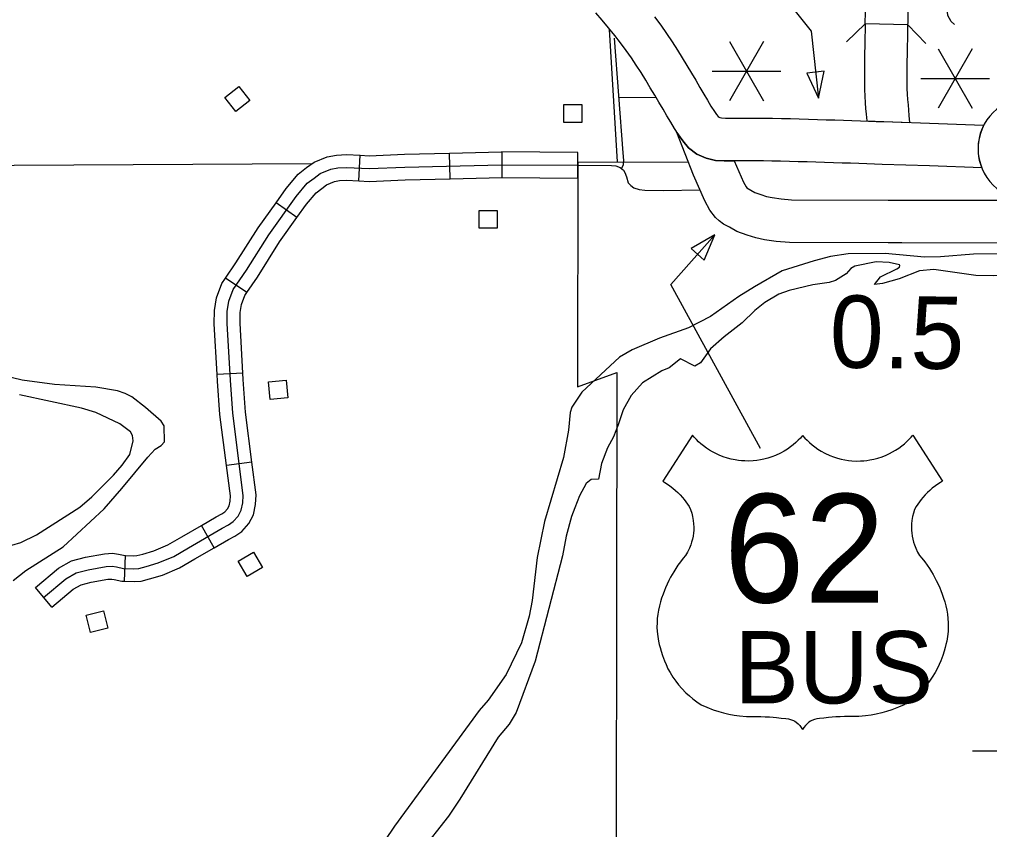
# Model space of a CAD drawing. Extents: x 1370130 to 1380143, y 377636 to 380256.
# Drawn here: x 1377311.5 to 1377470.1, y 378901.1 to 379033.5 of the extents above; entities that cross this region are included whole.
import ezdxf

# ---------------------------------------------------------------- set-up
doc = ezdxf.new("R2010")
doc.units = 0
for name, color, linetype in [('Level 10', 7, 'Continuous'), ('Level 15', 7, 'Continuous'), ('Level 22', 7, 'Continuous'), ('Level 24', 7, 'Continuous'), ('Level 31', 7, 'Continuous'), ('Level 32', 7, 'Continuous'), ('Level 33', 7, 'Continuous'), ('Level 34', 7, 'Continuous'), ('Level 35', 7, 'Continuous'), ('Level 37', 7, 'Continuous'), ('Level 48', 7, 'Continuous'), ('Level 5', 7, 'Continuous'), ('Level 56', 7, 'Continuous'), ('Level 6', 7, 'Continuous')]:
    doc.layers.add(name, color=color, linetype=linetype)

msp = doc.modelspace()

# ---------------------------------------------------------------- linework, layer by layer
at = {"layer": 'Level 10'}
for points in [[(1377456.75, 379032.66), (1377456.76, 379032.95), (1377456.79, 379034.23), (1377456.83, 379035.51), (1377456.87, 379036.8), (1377456.91, 379038.07), (1377456.96, 379039.32), (1377457.01, 379040.56), (1377457.07, 379041.81), (1377457.13, 379043.09), (1377457.17, 379044.44), (1377457.15, 379045.91), (1377456.99, 379047.47), (1377456.82, 379048.25)], [(1377449.75, 379032.77), (1377449.76, 379033.11), (1377449.79, 379034.41), (1377449.83, 379035.72), (1377449.87, 379037.02), (1377449.91, 379038.32), (1377449.96, 379039.6), (1377450.02, 379040.88), (1377450.08, 379042.14), (1377450.13, 379043.37), (1377450.17, 379044.49), (1377450.15, 379045.5), (1377450.06, 379046.39), (1377449.98, 379046.79)], [(1377456.75, 379032.62), (1377449.75, 379032.77), (1377449.73, 379031.81), (1377449.7, 379030.52), (1377449.68, 379029.22), (1377449.66, 379027.94), (1377449.64, 379026.69), (1377449.62, 379025.48), (1377449.62, 379024.32), (1377449.63, 379023.2), (1377449.64, 379022.07), (1377449.68, 379020.95), (1377449.75, 379019.9), (1377449.83, 379018.93), (1377449.92, 379018.04), (1377450.02, 379016.91), (1377452.81, 379016.8), (1377457.05, 379016.65)], [(1377457.05, 379016.65), (1377456.97, 379017.81), (1377456.89, 379018.68), (1377456.81, 379019.56), (1377456.73, 379020.43), (1377456.67, 379021.32), (1377456.64, 379022.24), (1377456.63, 379023.25), (1377456.62, 379024.32), (1377456.62, 379025.43), (1377456.64, 379026.6), (1377456.66, 379027.84), (1377456.68, 379029.09), (1377456.7, 379030.37), (1377456.75, 379032.62)]]:
    msp.add_lwpolyline(points, dxfattribs=at)
at = {"layer": 'Level 15'}
for points in [[(1377419.17, 379014.76), (1377418.58, 379015.69), (1377417.97, 379016.71), (1377417.35, 379017.76), (1377416.72, 379018.85), (1377416.05, 379019.96), (1377415.36, 379021.13), (1377414.63, 379022.33), (1377413.88, 379023.57), (1377413.12, 379024.81), (1377412.34, 379026.03), (1377411.53, 379027.24), (1377410.68, 379028.45), (1377409.77, 379029.66), (1377408.81, 379030.89), (1377407.8, 379032.13), (1377406.74, 379033.39), (1377405.75, 379034.57)], [(1377415.33, 379033.92), (1377416.34, 379032.57), (1377417.29, 379031.22), (1377418.21, 379029.86), (1377419.06, 379028.51), (1377419.85, 379027.21), (1377420.62, 379025.96), (1377421.35, 379024.74), (1377422.06, 379023.56), (1377422.75, 379022.4), (1377423.39, 379021.3), (1377423.99, 379020.29), (1377424.55, 379019.35), (1377425.1, 379018.48)], [(1377425, 379018.62), (1377425.47, 379017.95), (1377425.75, 379017.63), (1377425.87, 379017.53), (1377425.98, 379017.48), (1377426.28, 379017.42), (1377426.93, 379017.38), (1377427.95, 379017.38), (1377429.17, 379017.39), (1377430.45, 379017.38), (1377431.79, 379017.38), (1377433.18, 379017.37), (1377434.61, 379017.35), (1377436.06, 379017.33), (1377437.53, 379017.29), (1377438.98, 379017.26), (1377440.47, 379017.23), (1377441.95, 379017.17), (1377443.37, 379017.11), (1377444.78, 379017.08), (1377446.19, 379017.04), (1377447.59, 379017), (1377448.97, 379016.95), (1377450.3, 379016.9), (1377451.57, 379016.85), (1377452.81, 379016.8), (1377458.77, 379016.59), (1377469.12, 379016.22), (1377468.92, 379015.8), (1377468.76, 379015.41), (1377468.57, 379014.87), (1377468.45, 379014.45), (1377468.31, 379013.79), (1377468.26, 379013.39), (1377468.22, 379013), (1377468.2, 379012.49), (1377468.23, 379011.67), (1377468.3, 379011.08), (1377468.41, 379010.48), (1377468.54, 379009.99), (1377468.69, 379009.54), (1377468.81, 379009.24)], [(1377455.72, 378996.98), (1377453.49, 378996.99), (1377437.37, 378997.03), (1377435.18, 378997.23), (1377433.32, 378997.51), (1377431.87, 378997.81), (1377430.49, 378998.24), (1377428.76, 378998.85), (1377427.59, 378999.53), (1377426.62, 379000.07), (1377425.86, 379000.57), (1377425.28, 379001.16), (1377424.38, 379002.34), (1377423.57, 379003.86), (1377421.71, 379008.04), (1377418.99, 379015.04), (1377419.26, 379014.62), (1377419.94, 379013.64), (1377420.9, 379012.53), (1377422.21, 379011.51), (1377423.74, 379010.81), (1377425.29, 379010.47), (1377426.72, 379010.37), (1377427.99, 379010.38), (1377428.33, 379010.39)], [(1377468.81, 379009.24), (1377460.28, 379009.59), (1377452.54, 379009.8), (1377451.29, 379009.85), (1377450.01, 379009.91), (1377448.7, 379009.96), (1377447.37, 379010.01), (1377446, 379010.04), (1377444.59, 379010.08), (1377443.13, 379010.12), (1377441.68, 379010.18), (1377440.26, 379010.23), (1377438.82, 379010.26), (1377437.36, 379010.3), (1377435.93, 379010.33), (1377434.52, 379010.35), (1377433.11, 379010.37), (1377431.75, 379010.38), (1377430.43, 379010.38), (1377429.18, 379010.39), (1377427.99, 379010.38), (1377426.72, 379010.37), (1377425.29, 379010.47), (1377423.74, 379010.81), (1377422.21, 379011.51), (1377420.9, 379012.53), (1377419.94, 379013.64), (1377419.26, 379014.62), (1377419.17, 379014.76)], [(1377428.33, 379010.39), (1377429.86, 379006.93), (1377430.29, 379006.14), (1377430.42, 379005.97), (1377431.04, 379005.62), (1377431.71, 379005.24), (1377432.71, 379004.88), (1377433.63, 379004.59), (1377434.55, 379004.4), (1377436.02, 379004.18), (1377437.69, 379004.03), (1377453.5, 379003.99), (1377455.74, 379003.98)], [(1377479.75, 379004.6), (1377479.7, 379003.36), (1377479.68, 379002.12), (1377479.51, 379001.19), (1377479.31, 379000.33), (1377478.93, 378999.56), (1377478.36, 378998.77), (1377477.86, 378998.27), (1377477.08, 378997.73), (1377476.48, 378997.36), (1377475.75, 378997.11), (1377475.02, 378996.98), (1377474.45, 378996.94), (1377472.24, 378996.94), (1377455.72, 378996.98)], [(1377455.74, 379003.98), (1377472.25, 379003.94), (1377472.71, 379003.94), (1377472.75, 379004.91), (1377473.23, 379004.69), (1377473.63, 379004.52), (1377474.03, 379004.39), (1377474.5, 379004.25), (1377474.97, 379004.14), (1377475.48, 379004.06), (1377475.82, 379004.02), (1377476.14, 379004), (1377476.56, 379003.98), (1377477.1, 379004), (1377477.54, 379004.04), (1377478.11, 379004.12), (1377478.51, 379004.21), (1377479.03, 379004.34), (1377479.43, 379004.48), (1377479.75, 379004.6)]]:
    msp.add_lwpolyline(points, dxfattribs=at)
at = {"layer": 'Level 22'}
for points in [[(1377432.62, 378963.36), (1377418, 378990.2), (1377425.2, 378998.32)], [(1377439.53, 378965.49), (1377439.16, 378965.08), (1377438.81, 378964.72), (1377438.41, 378964.34), (1377437.97, 378963.97), (1377437.56, 378963.65), (1377437.05, 378963.29), (1377436.51, 378962.95), (1377435.89, 378962.62), (1377435.11, 378962.25), (1377434.5, 378962.02), (1377433.82, 378961.8), (1377433.2, 378961.63), (1377432.63, 378961.52), (1377432.02, 378961.42), (1377431.47, 378961.37), (1377430.7, 378961.33), (1377430.09, 378961.34), (1377429.55, 378961.37), (1377429.03, 378961.43), (1377428.51, 378961.5), (1377427.86, 378961.64), (1377427.26, 378961.79), (1377426.52, 378962.03), (1377425.89, 378962.28), (1377425.33, 378962.54), (1377424.81, 378962.81), (1377424.33, 378963.09), (1377423.79, 378963.45), (1377423.3, 378963.81), (1377422.88, 378964.15), (1377422.52, 378964.47), (1377422.16, 378964.82), (1377421.8, 378965.2), (1377421.51, 378965.53), (1377416.66, 378958.04), (1377417.01, 378957.83), (1377417.42, 378957.56), (1377417.81, 378957.28), (1377418.33, 378956.88), (1377418.75, 378956.52), (1377419.12, 378956.17), (1377419.49, 378955.79), (1377419.88, 378955.37), (1377420.15, 378955.03), (1377420.43, 378954.68), (1377420.7, 378954.3), (1377420.97, 378953.89), (1377421.22, 378953.42), (1377421.41, 378952.83), (1377421.55, 378952.25), (1377421.66, 378951.63), (1377421.71, 378951.06), (1377421.73, 378950.5), (1377421.72, 378949.98), (1377421.68, 378949.57), (1377421.62, 378949.06), (1377421.52, 378948.58), (1377421.39, 378948.06), (1377421.24, 378947.6), (1377421.04, 378947.09), (1377420.73, 378946.43), (1377420.4, 378945.91), (1377420.01, 378945.44), (1377419.54, 378944.83), (1377419.15, 378944.3), (1377418.79, 378943.77), (1377418.46, 378943.24), (1377418.19, 378942.77), (1377417.94, 378942.33), (1377417.67, 378941.81), (1377417.38, 378941.2), (1377417.11, 378940.6), (1377416.93, 378940.15), (1377416.72, 378939.58), (1377416.48, 378938.89), (1377416.3, 378938.31), (1377416.12, 378937.67), (1377415.96, 378936.94), (1377415.85, 378936.28), (1377415.77, 378935.6), (1377415.73, 378934.85), (1377415.72, 378934.15), (1377415.75, 378933.47), (1377415.84, 378932.66), (1377415.96, 378931.9), (1377416.09, 378931.32), (1377416.22, 378930.82), (1377416.39, 378930.25), (1377416.61, 378929.54), (1377416.93, 378928.67), (1377417.2, 378928.04), (1377417.52, 378927.38), (1377417.88, 378926.74), (1377418.33, 378926.01), (1377418.8, 378925.33), (1377419.26, 378924.74), (1377419.78, 378924.14), (1377420.45, 378923.44), (1377421.02, 378922.92), (1377421.6, 378922.43)], [(1377439.53, 378965.49), (1377439.89, 378965.08), (1377440.25, 378964.72), (1377440.65, 378964.34), (1377441.08, 378963.97), (1377441.5, 378963.65), (1377442, 378963.29), (1377442.54, 378962.95), (1377443.16, 378962.62), (1377443.95, 378962.25), (1377444.55, 378962.02), (1377445.23, 378961.8), (1377445.85, 378961.63), (1377446.42, 378961.52), (1377447.03, 378961.42), (1377447.59, 378961.37), (1377448.35, 378961.33), (1377448.97, 378961.34), (1377449.51, 378961.37), (1377450.02, 378961.43), (1377450.54, 378961.5), (1377451.19, 378961.64), (1377451.8, 378961.79), (1377452.53, 378962.03), (1377453.16, 378962.28), (1377453.72, 378962.54), (1377454.24, 378962.81), (1377454.72, 378963.09), (1377455.26, 378963.45), (1377455.75, 378963.81), (1377456.17, 378964.15), (1377456.53, 378964.47), (1377456.9, 378964.82), (1377457.25, 378965.2), (1377457.54, 378965.53), (1377462.39, 378958.04), (1377462.04, 378957.83), (1377461.63, 378957.56), (1377461.24, 378957.28), (1377460.72, 378956.88), (1377460.3, 378956.52), (1377459.94, 378956.17), (1377459.56, 378955.79), (1377459.18, 378955.37), (1377458.9, 378955.03), (1377458.63, 378954.68), (1377458.35, 378954.3), (1377458.08, 378953.89), (1377457.84, 378953.42), (1377457.65, 378952.83), (1377457.5, 378952.25), (1377457.4, 378951.63), (1377457.34, 378951.06), (1377457.32, 378950.5), (1377457.33, 378949.98), (1377457.37, 378949.57), (1377457.44, 378949.06), (1377457.53, 378948.58), (1377457.67, 378948.06), (1377457.81, 378947.6), (1377458.01, 378947.09), (1377458.33, 378946.43), (1377458.65, 378945.91), (1377459.04, 378945.44), (1377459.51, 378944.83), (1377459.9, 378944.3), (1377460.26, 378943.77), (1377460.59, 378943.24), (1377460.87, 378942.77), (1377461.11, 378942.33), (1377461.38, 378941.81), (1377461.67, 378941.2), (1377461.94, 378940.6), (1377462.12, 378940.15), (1377462.33, 378939.58), (1377462.57, 378938.89), (1377462.76, 378938.31), (1377462.93, 378937.67), (1377463.1, 378936.94), (1377463.2, 378936.28), (1377463.28, 378935.6), (1377463.33, 378934.85), (1377463.33, 378934.15), (1377463.3, 378933.47), (1377463.21, 378932.66), (1377463.09, 378931.9), (1377462.96, 378931.32), (1377462.83, 378930.82), (1377462.67, 378930.25), (1377462.44, 378929.54), (1377462.12, 378928.67), (1377461.85, 378928.04), (1377461.53, 378927.38), (1377461.18, 378926.74), (1377460.72, 378926.01), (1377460.25, 378925.33), (1377459.79, 378924.74), (1377459.27, 378924.14), (1377458.6, 378923.44), (1377458.04, 378922.92), (1377457.45, 378922.43)], [(1377421.6, 378922.43), (1377422.21, 378921.97), (1377422.94, 378921.49), (1377423.86, 378921.08), (1377424.93, 378920.67), (1377425.81, 378920.38), (1377426.59, 378920.16), (1377427.49, 378919.96), (1377428.32, 378919.8), (1377429.22, 378919.68), (1377430.35, 378919.58), (1377431.22, 378919.55), (1377431.96, 378919.56), (1377432.68, 378919.55), (1377433.41, 378919.53), (1377434.09, 378919.49), (1377434.69, 378919.45), (1377435.28, 378919.4), (1377436.03, 378919.32), (1377436.77, 378919.23), (1377437.21, 378919.17), (1377437.57, 378919.1), (1377438.01, 378918.92), (1377438.27, 378918.78), (1377438.49, 378918.63), (1377438.79, 378918.39), (1377439.08, 378918.09), (1377439.31, 378917.79), (1377439.53, 378917.44)], [(1377457.45, 378922.43), (1377456.84, 378921.97), (1377456.11, 378921.49), (1377455.2, 378921.08), (1377454.12, 378920.67), (1377453.25, 378920.38), (1377452.46, 378920.16), (1377451.57, 378919.96), (1377450.73, 378919.8), (1377449.83, 378919.68), (1377448.7, 378919.58), (1377447.83, 378919.55), (1377447.09, 378919.56), (1377446.37, 378919.55), (1377445.65, 378919.53), (1377444.96, 378919.49), (1377444.36, 378919.45), (1377443.78, 378919.4), (1377443.02, 378919.32), (1377442.29, 378919.23), (1377441.85, 378919.17), (1377441.48, 378919.1), (1377441.04, 378918.92), (1377440.79, 378918.78), (1377440.57, 378918.63), (1377440.26, 378918.39), (1377439.98, 378918.09), (1377439.74, 378917.79), (1377439.53, 378917.44)]]:
    msp.add_lwpolyline(points, dxfattribs=at)
msp.add_lwpolyline([(1377421.29, 378996.06), (1377423.43, 378994.16), (1377425.2, 378998.32)], close=True, dxfattribs=at)
at = {"layer": 'Level 24'}
msp.add_arc((1377476.6, 379012.38), 8.4, 90, 270, dxfattribs=at)
at = {"layer": 'Level 31'}
msp.add_line((1377390.37, 379011.87), (1377390.34, 379007.67), dxfattribs=at)
for points in [[(1377390.34, 379007.67), (1377402.77, 379007.57), (1377402.78, 379011.77)], [(1377402.78, 379011.77), (1377390.37, 379011.87)], [(1377390.36, 379009.77), (1377402.78, 379009.67)]]:
    msp.add_lwpolyline(points, dxfattribs=at)
at = {"layer": 'Level 32'}
for p, q in [((1377366.98, 379007.11), (1377367.2, 379011.3)), ((1377381.92, 379007.46), (1377381.82, 379011.66)), ((1377356.87, 379001.11), (1377353.46, 379003.55)), ((1377348.67, 378988.87), (1377345.21, 378991.23)), ((1377348.02, 378975.69), (1377343.83, 378975.46)), ((1377349.52, 378961.14), (1377345.35, 378960.61)), ((1377343.36, 378947.16), (1377341.25, 378950.79)), ((1377328.66, 378941.68), (1377328.82, 378945.87)), ((1377316.81, 378937.43), (1377314.11, 378940.65))]:
    msp.add_line(p, q, dxfattribs=at)
for points in [[(1377353.46, 379003.55), (1377355.1, 379005.86), (1377357.09, 379008.24), (1377358.44, 379009.28), (1377359.67, 379010.16), (1377361.81, 379011.04), (1377363.33, 379011.34), (1377364.99, 379011.42), (1377367.2, 379011.3)], [(1377367.2, 379011.3), (1377368.68, 379011.22), (1377374.44, 379011.48), (1377381.82, 379011.66)], [(1377381.82, 379011.66), (1377390.31, 379011.87)], [(1377315.46, 378939.04), (1377319.1, 378942.09), (1377320.79, 378943.04), (1377322.77, 378943.56), (1377325.69, 378944.08), (1377326.67, 378944.14), (1377327.35, 378944.04), (1377328.52, 378943.78), (1377330.2, 378943.72), (1377331.05, 378943.78), (1377332.22, 378944.08), (1377334.2, 378944.66), (1377336.73, 378945.73), (1377339.13, 378947.13), (1377344.65, 378950.35), (1377345.66, 378950.87), (1377346.47, 378951.42), (1377347.25, 378952.3), (1377347.77, 378953.27), (1377348.03, 378954.51), (1377348.1, 378955.71), (1377346.37, 378969.13), (1377345.99, 378974.52), (1377345.47, 378983.81), (1377345.49, 378985.77), (1377345.76, 378987.45), (1377346.47, 378989.37), (1377348.65, 378992.55), (1377352.28, 378998.3), (1377356.77, 379004.57), (1377358.55, 379006.72), (1377359.69, 379007.59), (1377360.69, 379008.31), (1377362.42, 379009.02), (1377363.58, 379009.25), (1377364.98, 379009.31), (1377368.67, 379009.12), (1377374.51, 379009.38), (1377390.36, 379009.77)], [(1377381.92, 379007.46), (1377390.41, 379007.67)], [(1377356.87, 379001.11), (1377358.43, 379003.29), (1377360.02, 379005.19), (1377360.94, 379005.9), (1377361.72, 379006.46), (1377363.03, 379007), (1377363.84, 379007.16), (1377364.97, 379007.21), (1377366.98, 379007.11)], [(1377366.98, 379007.11), (1377368.66, 379007.02), (1377374.58, 379007.28), (1377381.92, 379007.46)], [(1377345.21, 378991.23), (1377346.89, 378993.7), (1377350.54, 378999.47), (1377353.46, 379003.55)], [(1377348.67, 378988.87), (1377350.4, 378991.4), (1377354.03, 378997.13), (1377356.87, 379001.11)], [(1377343.83, 378975.46), (1377343.36, 378983.77), (1377343.4, 378985.95), (1377343.72, 378987.98), (1377344.59, 378990.34), (1377345.21, 378991.23)], [(1377348.02, 378975.69), (1377347.57, 378983.85), (1377347.59, 378985.59), (1377347.8, 378986.91), (1377348.35, 378988.39), (1377348.67, 378988.87)], [(1377345.35, 378960.61), (1377344.28, 378968.92), (1377343.89, 378974.38), (1377343.83, 378975.46)], [(1377349.52, 378961.14), (1377348.47, 378969.33), (1377348.08, 378974.65), (1377348.02, 378975.69)], [(1377341.25, 378950.79), (1377343.64, 378952.19), (1377344.58, 378952.67), (1377345.08, 378953.01), (1377345.52, 378953.5), (1377345.78, 378954), (1377345.94, 378954.78), (1377345.99, 378955.63), (1377345.35, 378960.61)], [(1377343.36, 378947.16), (1377345.67, 378948.51), (1377346.74, 378949.06), (1377347.87, 378949.83), (1377348.99, 378951.09), (1377349.76, 378952.55), (1377350.12, 378954.23), (1377350.2, 378955.78), (1377349.52, 378961.14)], [(1377328.82, 378945.87), (1377330.16, 378945.82), (1377330.71, 378945.86), (1377331.67, 378946.1), (1377333.49, 378946.64), (1377335.79, 378947.62), (1377338.08, 378948.95), (1377341.25, 378950.79)], [(1377314.11, 378940.65), (1377317.9, 378943.83), (1377320, 378945), (1377322.32, 378945.61), (1377325.44, 378946.16), (1377326.74, 378946.25), (1377327.72, 378946.11), (1377328.79, 378945.88), (1377328.82, 378945.87)], [(1377328.66, 378941.68), (1377330.24, 378941.62), (1377331.39, 378941.7), (1377332.77, 378942.05), (1377334.91, 378942.68), (1377337.67, 378943.85), (1377340.19, 378945.32), (1377343.36, 378947.16)], [(1377316.81, 378937.43), (1377320.3, 378940.36), (1377321.58, 378941.07), (1377323.22, 378941.5), (1377325.95, 378941.99), (1377326.59, 378942.03), (1377326.97, 378941.98), (1377328.25, 378941.69), (1377328.66, 378941.68)]]:
    msp.add_lwpolyline(points, dxfattribs=at)
at = {"layer": 'Level 33'}
msp.add_lwpolyline([(1377402.78, 379009.67), (1377408.28, 379009.63), (1377409.01, 379009.59), (1377409.73, 379009.33), (1377410.24, 379008.86), (1377410.49, 379008.48), (1377410.75, 379007.76), (1377411, 379006.82), (1377411.43, 379006.36), (1377411.94, 379005.97), (1377412.83, 379005.72), (1377413.76, 379005.59), (1377416.75, 379005.55), (1377422.77, 379005.65)], dxfattribs=at)
at = {"layer": 'Level 34'}
for points in [[(1377464.38, 379032.69), (1377463.81, 379033.16), (1377463.29, 379034.14), (1377463.12, 379035.87), (1377463.34, 379040.23)], [(1377409.93, 379009.15), (1377410.25, 379009.72), (1377410.3, 379010.46), (1377410.21, 379011.73), (1377408.79, 379030.47)], [(1377415.62, 379020.7), (1377409.52, 379020.74)]]:
    msp.add_lwpolyline(points, dxfattribs=at)
at = {"layer": 'Level 35'}
for points in [[(1377476.08, 378995.19), (1377467.48, 378995.12), (1377462.04, 378994.73), (1377459.46, 378994.67), (1377453.01, 378995.27), (1377446.97, 378995.2), (1377444.06, 378994.77), (1377441.41, 378994.04), (1377436.19, 378992.42), (1377431.66, 378989.82), (1377429.11, 378988.2), (1377424.46, 378984.93), (1377420.87, 378983.12), (1377416.16, 378981.42), (1377411.67, 378979.5), (1377409.59, 378978.28), (1377403.44, 378972.59), (1377401.8, 378970.14), (1377401.54, 378969.27), (1377401.26, 378966.37), (1377400.43, 378961.89), (1377397.32, 378951.45), (1377396.12, 378945.58), (1377395.34, 378938.52), (1377394.83, 378935.99), (1377393.6, 378931.58), (1377391.09, 378926.42), (1377388.11, 378922.24), (1377386.63, 378920.55), (1377372.8, 378901.63), (1377371.25, 378899.32)], [(1377455.32, 378991.13), (1377452.61, 378990.32), (1377451.26, 378990.18), (1377452.25, 378991.46), (1377454.95, 378992.73), (1377455.34, 378993.02), (1377455.44, 378993.27), (1377455.38, 378993.38), (1377453.66, 378993.79), (1377451.55, 378993.89), (1377448.08, 378993.17), (1377447.42, 378992.79), (1377446.62, 378991.91), (1377444.9, 378990.86), (1377443.87, 378990.53), (1377441.21, 378990.14), (1377437.32, 378989.21), (1377435.62, 378988.62), (1377433.34, 378987.25), (1377431.74, 378985.93), (1377429.62, 378983.89), (1377426.69, 378981.64), (1377424.48, 378979.68), (1377422.84, 378977.4), (1377421.89, 378976.85), (1377419.57, 378978.04), (1377417.71, 378976.57), (1377416.49, 378976.09), (1377413.35, 378974.09), (1377411.51, 378972.03), (1377410.18, 378969.7), (1377409.39, 378967.22), (1377408.59, 378965.26), (1377407.64, 378963.5), (1377406.66, 378960.9), (1377406.15, 378958.37), (1377404.99, 378958.28), (1377404.14, 378957.65), (1377403.08, 378955.61), (1377402.28, 378953.65), (1377401.77, 378952.27), (1377400.88, 378949.02), (1377400.28, 378945.84), (1377395.79, 378928.6), (1377392.68, 378920.23), (1377391.56, 378918.3), (1377389.78, 378916.18), (1377383.5, 378906.06), (1377381.62, 378903.27), (1377376.99, 378897.39)], [(1377491.37, 378986.32), (1377485.09, 378989.94), (1377483.22, 378990.65), (1377478.93, 378992), (1377476.59, 378992.31), (1377474.57, 378992.13), (1377472.58, 378991.72), (1377470.7, 378991.6), (1377467.86, 378991.68), (1377460.96, 378992.66), (1377458.66, 378992.44), (1377455.32, 378991.13)], [(1377310.51, 378941.82), (1377312.56, 378943.41), (1377318.66, 378947.32), (1377325.36, 378953.53), (1377328.24, 378956.81), (1377332.47, 378961.95), (1377333.7, 378963.24), (1377334.67, 378963.88), (1377335.2, 378964.45), (1377335.14, 378967.06), (1377334.65, 378967.86), (1377332.13, 378970.06), (1377329.88, 378971.81), (1377328.77, 378972.34), (1377327.53, 378972.79), (1377324, 378973.42), (1377317.22, 378973.81), (1377311.98, 378974.54), (1377306.73, 378975.81)], [(1377310.28, 378947.57), (1377311.73, 378948.02), (1377314.32, 378949.28), (1377321.37, 378953.81), (1377323.35, 378955.48), (1377326.88, 378959), (1377328.31, 378960.66), (1377329.53, 378962.4), (1377330.08, 378964.6), (1377329.98, 378965.49), (1377329.68, 378966.1), (1377327.92, 378967.41), (1377324, 378969.24), (1377321.63, 378969.95), (1377311.5, 378972.15)]]:
    msp.add_lwpolyline(points, dxfattribs=at)
at = {"layer": 'Level 37'}
for points in [[(1377446.72, 379029.86), (1377449.75, 379032.77)], [(1377456.75, 379032.62), (1377459.66, 379029.59)]]:
    msp.add_lwpolyline(points, dxfattribs=at)
at = {"layer": 'Level 48'}
for p, q in [((1377433.16, 379029.91), (1377427.56, 379020.21)), ((1377427.56, 379029.91), (1377433.16, 379020.21)), ((1377467.26, 379028.7), (1377461.67, 379019)), ((1377461.67, 379028.7), (1377467.26, 379019)), ((1377424.76, 379025.06), (1377435.96, 379025.06)), ((1377458.87, 379023.85), (1377470.06, 379023.85)), ((1377467.32, 378913.98), (1377478.52, 378913.98))]:
    msp.add_line(p, q, dxfattribs=at)
msp.add_lwpolyline([(1377433.46, 379040.94), (1377440.91, 379031.61), (1377442.1, 379020.62)], dxfattribs=at)
msp.add_lwpolyline([(1377443.06, 379025.03), (1377440.22, 379024.72), (1377442.1, 379020.62)], close=True, dxfattribs=at)
at = {"layer": 'Level 5'}
for points in [[(1377261.95, 379009.43), (1377359.3, 379009.95)], [(1377409.25, 379010.21), (1377420.87, 379010.2)]]:
    msp.add_lwpolyline(points, dxfattribs=at)
at = {"layer": 'Level 56'}
for points in [[(1377346.86, 379018.46), (1377345.06, 379020.76), (1377347.37, 379022.56), (1377349.16, 379020.26)], [(1377400.5, 379016.66), (1377400.5, 379019.58), (1377403.42, 379019.58), (1377403.42, 379016.66)], [(1377386.67, 378999.37), (1377386.67, 379002.28), (1377389.59, 379002.28), (1377389.59, 378999.37)], [(1377355.11, 378974.55), (1377355.39, 378971.65), (1377352.48, 378971.37), (1377352.2, 378974.27)], [(1377349.77, 378946.43), (1377351.26, 378943.92), (1377348.74, 378942.43), (1377347.26, 378944.94)], [(1377325.26, 378936.85), (1377325.98, 378934.02), (1377323.15, 378933.3), (1377322.43, 378936.12)]]:
    msp.add_lwpolyline(points, close=True, dxfattribs=at)
at = {"layer": 'Level 6'}
for points in [[(1377402.78, 379010.18), (1377409.25, 379010.21), (1377407.97, 379031.86)], [(1377402.78, 379010.18), (1377402.71, 378973.48), (1377409.18, 378975.78)], [(1377409.18, 378975.78), (1377408.97, 378862.26), (1377419.72, 378862.54)]]:
    msp.add_lwpolyline(points, dxfattribs=at)

# ---------------------------------------------------------------- texts
at = {"layer": 'Level 22'}
for s, height, p in [('62', 17.741, (1377426.64, 378938.2)), ('BUS', 11.827, (1377428.35, 378921.7))]:
    msp.add_text(s, height=height, dxfattribs=at).set_placement(p)
at = {"layer": 'Level 48'}
msp.add_text('0.5', height=11.827, rotation=359.2836, dxfattribs=at).set_placement((1377443.91, 378976.61))

doc.saveas('drawing.dxf')
